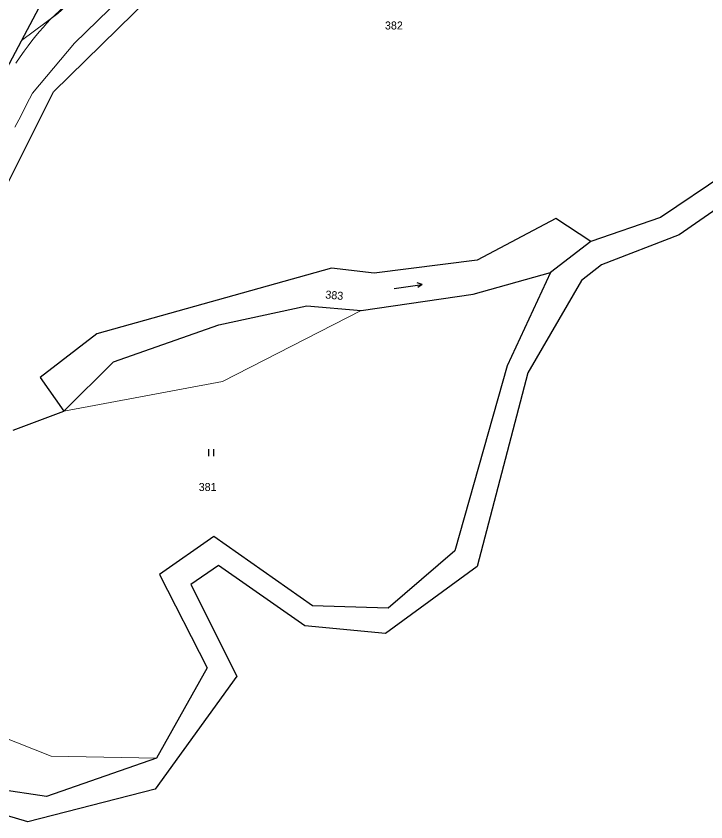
# Model space of a CAD drawing. Extents: x -504006 to -501322, y -1128098 to -1124665.
# Drawn here: x -502251.7 to -502105.3, y -1128030.8 to -1127859.7 of the extents above; entities that cross this region are included whole.
import ezdxf
from ezdxf.enums import TextEntityAlignment as Align

# ---------------------------------------------------------------- set-up
doc = ezdxf.new("R2010")
doc.units = 0
doc.header["$LTSCALE"] = 0.68
for name, color, linetype, lineweight in [('1', 7, 'Continuous', 25), ('13', 7, 'Continuous', 13), ('3', 7, 'Continuous', 25), ('4', 7, 'Continuous', 13)]:
    doc.layers.add(name, color=color, linetype=linetype, lineweight=lineweight)
doc.layers.add('2', color=7, linetype='Continuous')

msp = doc.modelspace()

# ---------------------------------------------------------------- linework, layer by layer
at = {"layer": '1'}
for p, q in [((-502243.76, -1127875.74), (-502185.36, -1127818.43)), ((-502246.89, -1127857.93), (-502268.68, -1127898.79)), ((-502261.01, -1127910.1), (-502243.76, -1127875.74)), ((-502085.63, -1127882.6), (-502114.93, -1127902.46)), ((-502082.66, -1127886.38), (-502110.91, -1127906.08)), ((-502137.15, -1127902.65), (-502153.82, -1127911.48)), ((-502129.69, -1127907.49), (-502137.15, -1127902.65)), ((-502114.93, -1127902.46), (-502129.69, -1127907.49)), ((-502110.91, -1127906.08), (-502127.42, -1127912.49)), ((-502129.69, -1127907.49), (-502138.24, -1127914.09)), ((-502153.82, -1127911.48), (-502175.69, -1127914.24)), ((-502184.78, -1127913.17), (-502234.6, -1127927.1)), ((-502175.69, -1127914.24), (-502184.78, -1127913.17)), ((-502127.42, -1127912.49), (-502131.67, -1127915.82)), ((-502154.66, -1127918.73), (-502138.24, -1127914.09)), ((-502138.24, -1127914.09), (-502147.49, -1127933.89)), ((-502131.67, -1127915.82), (-502143.09, -1127935.38)), ((-502178.47, -1127922.14), (-502154.66, -1127918.73)), ((-502208.67, -1127925.24), (-502189.96, -1127921.18)), ((-502189.96, -1127921.18), (-502178.47, -1127922.14)), ((-502231.07, -1127933.04), (-502208.67, -1127925.24)), ((-502234.6, -1127927.1), (-502246.63, -1127936.41)), ((-502241.62, -1127943.56), (-502231.07, -1127933.04)), ((-502147.49, -1127933.89), (-502158.58, -1127973.18)), ((-502143.09, -1127935.38), (-502153.84, -1127976.5)), ((-502246.63, -1127936.41), (-502241.62, -1127943.56)), ((-502252.35, -1127947.59), (-502241.62, -1127943.56)), ((-502209.73, -1127970.18), (-502221.29, -1127978.2)), ((-502188.77, -1127984.88), (-502209.73, -1127970.18)), ((-502158.58, -1127973.18), (-502172.69, -1127985.35)), ((-502208.78, -1127976.32), (-502214.6, -1127980.33)), ((-502190.44, -1127989.11), (-502208.78, -1127976.32)), ((-502221.29, -1127978.2), (-502211.18, -1127998.01)), ((-502153.84, -1127976.5), (-502173.31, -1127990.78)), ((-502214.6, -1127980.33), (-502204.83, -1127999.8)), ((-502172.69, -1127985.35), (-502188.77, -1127984.88)), ((-502173.31, -1127990.78), (-502190.44, -1127989.11)), ((-502211.18, -1127998.01), (-502221.9, -1128017.23)), ((-502204.83, -1127999.8), (-502222.2, -1128023.78)), ((-502221.9, -1128017.23), (-502245.25, -1128025.33)), ((-502245.25, -1128025.33), (-502258.41, -1128023.41)), ((-502222.2, -1128023.78), (-502249.21, -1128030.75)), ((-502249.21, -1128030.75), (-502263.31, -1128026.56))]:
    msp.add_line(p, q, dxfattribs=at)
at = {"layer": '13'}
msp.add_lwpolyline([(-502189.39, -1127804.79), (-502246.89, -1127857.93), (-502250.58, -1127864.85), (-502242.85, -1127859.14), (-502214.94, -1127833.48), (-502199.31, -1127818.14), (-502185.96, -1127804.4)], close=True, dxfattribs=at)
at = {"layer": '3'}
for p, q in [((-502165.501, -1127916.639), (-502166.399, -1127917.271)), ((-502210.771, -1127953.09), (-502210.771, -1127951.59)), ((-502209.77, -1127953.09), (-502209.77, -1127951.59))]:
    msp.add_line(p, q, dxfattribs=at)
msp.add_lwpolyline([(-502171.443, -1127917.474), (-502165.501, -1127916.639), (-502166.538, -1127916.278)], dxfattribs=at)
at = {"layer": '4'}
for p, q in [((-502244.4, -1127860.31), (-502197.74, -1127816.52)), ((-502192.89, -1127820.22), (-502239.3, -1127865.39)), ((-502239.3, -1127865.39), (-502248.26, -1127876.05)), ((-502207.87, -1127937.23), (-502178.47, -1127922.14)), ((-502241.62, -1127943.56), (-502207.87, -1127937.23)), ((-502265.62, -1128008.38), (-502244.31, -1128016.77)), ((-502244.31, -1128016.77), (-502221.9, -1128017.23))]:
    msp.add_line(p, q, dxfattribs=at)
for points in [[(-502251.795, -1127869.657), (-502250.901, -1127868.323), (-502250.024, -1127867.081), (-502249.18, -1127865.945), (-502248.356, -1127864.889), (-502247.539, -1127863.887), (-502246.745, -1127862.949), (-502245.961, -1127862.051), (-502245.174, -1127861.169), (-502244.4, -1127860.31)], [(-502248.26, -1127876.05), (-502249.497, -1127878.463), (-502250.744, -1127880.895), (-502251.966, -1127883.277)]]:
    msp.add_lwpolyline(points, dxfattribs=at)

# ---------------------------------------------------------------- texts
at = {"layer": '2'}
for s, p in [('382', (-502171.509, -1127862.505)), ('381', (-502211.059, -1127960.495))]:
    msp.add_text(s, height=1.7, dxfattribs=at).set_placement(p, align=Align.CENTER)
msp.add_text('383', height=1.7, rotation=355, dxfattribs=at).set_placement((-502184.2286, -1127919.7761), align=Align.CENTER)

doc.saveas('drawing.dxf')
